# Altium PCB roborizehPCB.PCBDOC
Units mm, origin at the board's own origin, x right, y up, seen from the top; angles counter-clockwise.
Board outline 18 x 16 mm, 2 copper layers (Top Layer, Bottom Layer); 5 components, 0 nets, 28 pads, 0 vias.
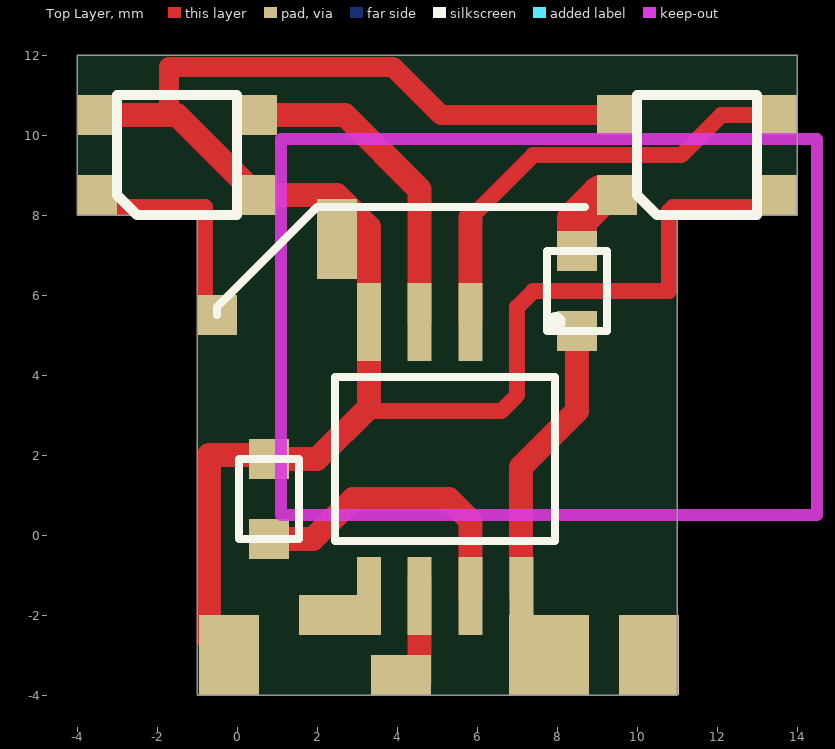
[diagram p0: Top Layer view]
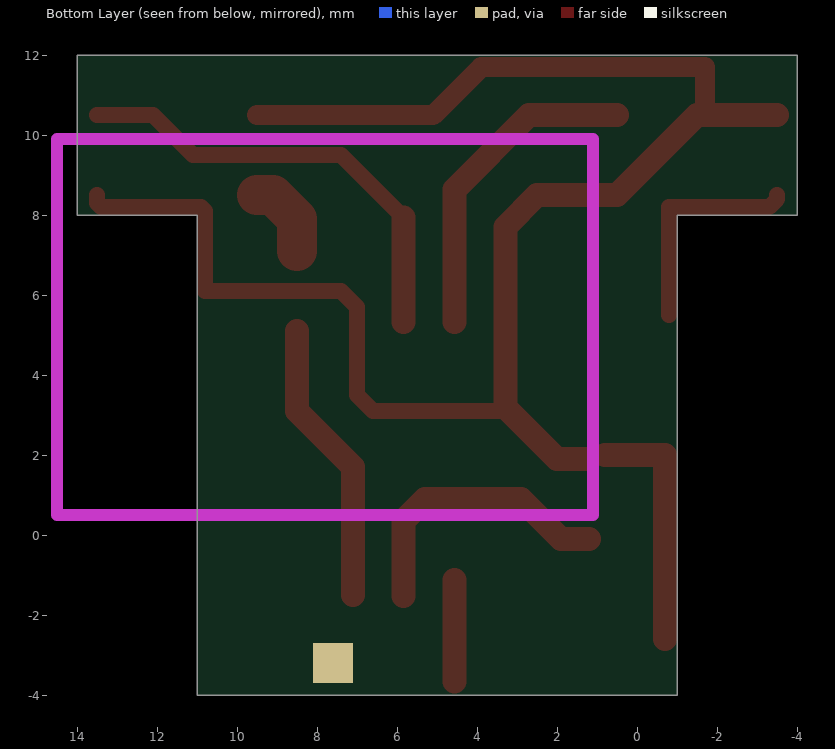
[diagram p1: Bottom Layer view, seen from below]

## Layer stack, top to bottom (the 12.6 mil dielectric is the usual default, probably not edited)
Top Layer: signal copper 0.0356
Dielectric: dielectric 0.32, FR-4, Dk 4.8
Bottom Layer: signal copper 0.0356

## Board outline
-1,-4 -1,8 -4,8 -4,12 14,12 14,8 11,8 11,-4

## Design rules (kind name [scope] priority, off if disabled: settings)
Clearance [All] p1: gap=0.2
ComponentClearance [All] p1: gap=0.254 collisioncheckmode=0
PolygonConnect [All] p1: connectstyle=Relief reliefconductorwidth=0.254 reliefentries=4 polygonreliefangle="90 Angle"
RoutingLayers [All] p1: top layer=Horizontal bottom layer=Vertical
RoutingVias [All] p1: holewidth=0.6 width=1 viastyle="Through Hole" minholewidth=0.711 minwidth=1.27 maxholewidth=0.711 maxwidth=1.27
SolderMaskExpansion [All] p1: expansion=0.102
TestPointUsage [All] p1: valid=0 allowmultiple=FALSE
Testpoint [All] p1: side=15 testpointundercomponent=TRUE minsize=1.016 maxsize=2.54 preferedsize=1.524 minholesize=0 maxholesize=1.016 preferedholesize=0.813 testpointgrid=0.025 style=1023 order=-539222988
Width [All] p1: maxlimit=0.2 minlimit=0.2 preferedwidth=0.2
16 further rules are at their usual default settings.

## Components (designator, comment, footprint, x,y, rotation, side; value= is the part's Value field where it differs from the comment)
? "Comment" 8S2 5.2,1.9 r180 top
? "Comment" sensor 12,9 r0 top
? "Comment" sensor -1,9 r0 top
? "Comment" res 9,6.6 r270 top
? "Comment" res 1.3,1.4 r270 top

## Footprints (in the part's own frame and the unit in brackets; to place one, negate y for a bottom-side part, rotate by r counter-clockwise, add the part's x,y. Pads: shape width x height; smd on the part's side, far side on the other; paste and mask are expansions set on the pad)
8S2 [mm] "Small Outline; 8 Leads; Body Width 5.3 mm; Pitch 1.27 mm"
  rect 0x0 smd: 1(-1.905,-3.425)
  rect 0.6x1.95 smd: 2(-0.635,-3.425) 3(0.635,-3.425) 5(1.905,3.425) 6(0.635,3.425) 7(-0.635,3.425) +(-1.905,3.425) -(1.905,-3.425)
  silkscreen extent -2.89,-3.55 2.75,2.05
res [mm]
  rect 1x1 smd: 1(-0.5,-0.5) 2(1.5,-0.5)
  silkscreen extent -0.5,-1.25 1.5,0.25
sensor [mm] "sensor"
  rect 1x1 smd: +r(-2.5,-0.5) -(-2.5,1.5) -(1.5,-0.5) m(1.5,1.5)
  silkscreen extent -2,-1 1,2

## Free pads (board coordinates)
  rect 1x1 all layers, no hole: 1(7.6,-3.2)
  rect 1x1 smd: 6(-0.5,5.5)
  rect 1.5x1 smd: 6(2.3,-2) 6(4.1,-3.5)
  rect 1x2 smd: 6(2.5,7.4)
  rect 2x2 smd: 6(7.8,-3)
  rect 1.5x2 smd: ""(-0.2,-3) ""(10.3,-3)

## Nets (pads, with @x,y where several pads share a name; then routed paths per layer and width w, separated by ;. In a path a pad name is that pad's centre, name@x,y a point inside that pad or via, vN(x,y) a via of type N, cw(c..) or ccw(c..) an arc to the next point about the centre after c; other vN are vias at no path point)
pads on no net: ?.1 ?.2 ?.3 ?.5 ?.6 ?.7 ?.+ ?.+r ?.- ?.m
copper on no net: | length 93.2
  Top Layer w0.4: -3.5,8.5 -3.5,8.4 -3.3,8.2 -0.8,8.2 -0.8,5.5 ; 3.2,3.1 6.6,3.1 7,3.5 7,5.7 7.4,6.1 9.6,6.1 10.8,6.1 10.8,8.1 10.9,8.2 13.4,8.2 13.5,8.3 13.5,8.5 ; 5.835,7.935 7.4,9.5 11.1,9.5 12.1,10.5 13.5,10.5
  Top Layer w0.5: -1.7,10.5 -1.7,11.7 3.9,11.7 5.1,10.5 9.5,10.5
  Top Layer w0.6: -3.5,10.5 -1.5,10.5 0.5,8.5 2.5,8.5 3.295,7.705 3.295,5.325 3.295,3.195 2,1.9 1.2,1.9 ; -0.7,-2.6 -0.7,2 0.8,2 ; 0.5,10.5 2.7,10.5 4.565,8.635 4.565,5.325 ; 1.2,-0.1 1.9,-0.1 2.9,0.9 5.3,0.9 5.835,0.365 5.835,-1.525 ; 4.565,-3.665 4.565,-1.125 ; 5.835,5.325 5.835,7.935 ; 7.1,-1.5 7.1,1.7 8.5,3.1 8.5,5.1
  Top Layer w1: 8.5,7.1 8.5,7.9 9.1,8.5 9.5,8.5

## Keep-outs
Keep-Out Layer:
  lines w0.3: 1.1,0.5 14.5,0.5 14.5,9.9 1.1,9.9 1.1,0.5 ; 6.2,-29.7 6.2,-20.3 21.6,-20.3 21.6,-29.7 6.2,-29.7

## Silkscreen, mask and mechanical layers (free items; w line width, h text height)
Top Overlay:
  lines w0.2: -0.5,5.5 -0.5,5.7 2,8.2 8.7,8.2
Drill Drawing:
  text ".LEGEND" at 20.88,4.28 h1.52
  text "Drill Drawing." at 20.88,1.74 h1.52
  text ".LEGEND" at 27.98,-25.92 h1.52
  text "Drill Drawing." at 27.98,-28.46 h1.52

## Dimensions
1.1,0.5 to 14.5,0.5 on Mechanical 1
1.1,0.5 to 1.1,9.9 on Mechanical 1
27.98,-28.46 to 27.98,-28.46 on Mechanical 1
27.98,-28.46 to 27.98,-28.46 on Mechanical 1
